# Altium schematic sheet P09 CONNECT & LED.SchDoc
size A2
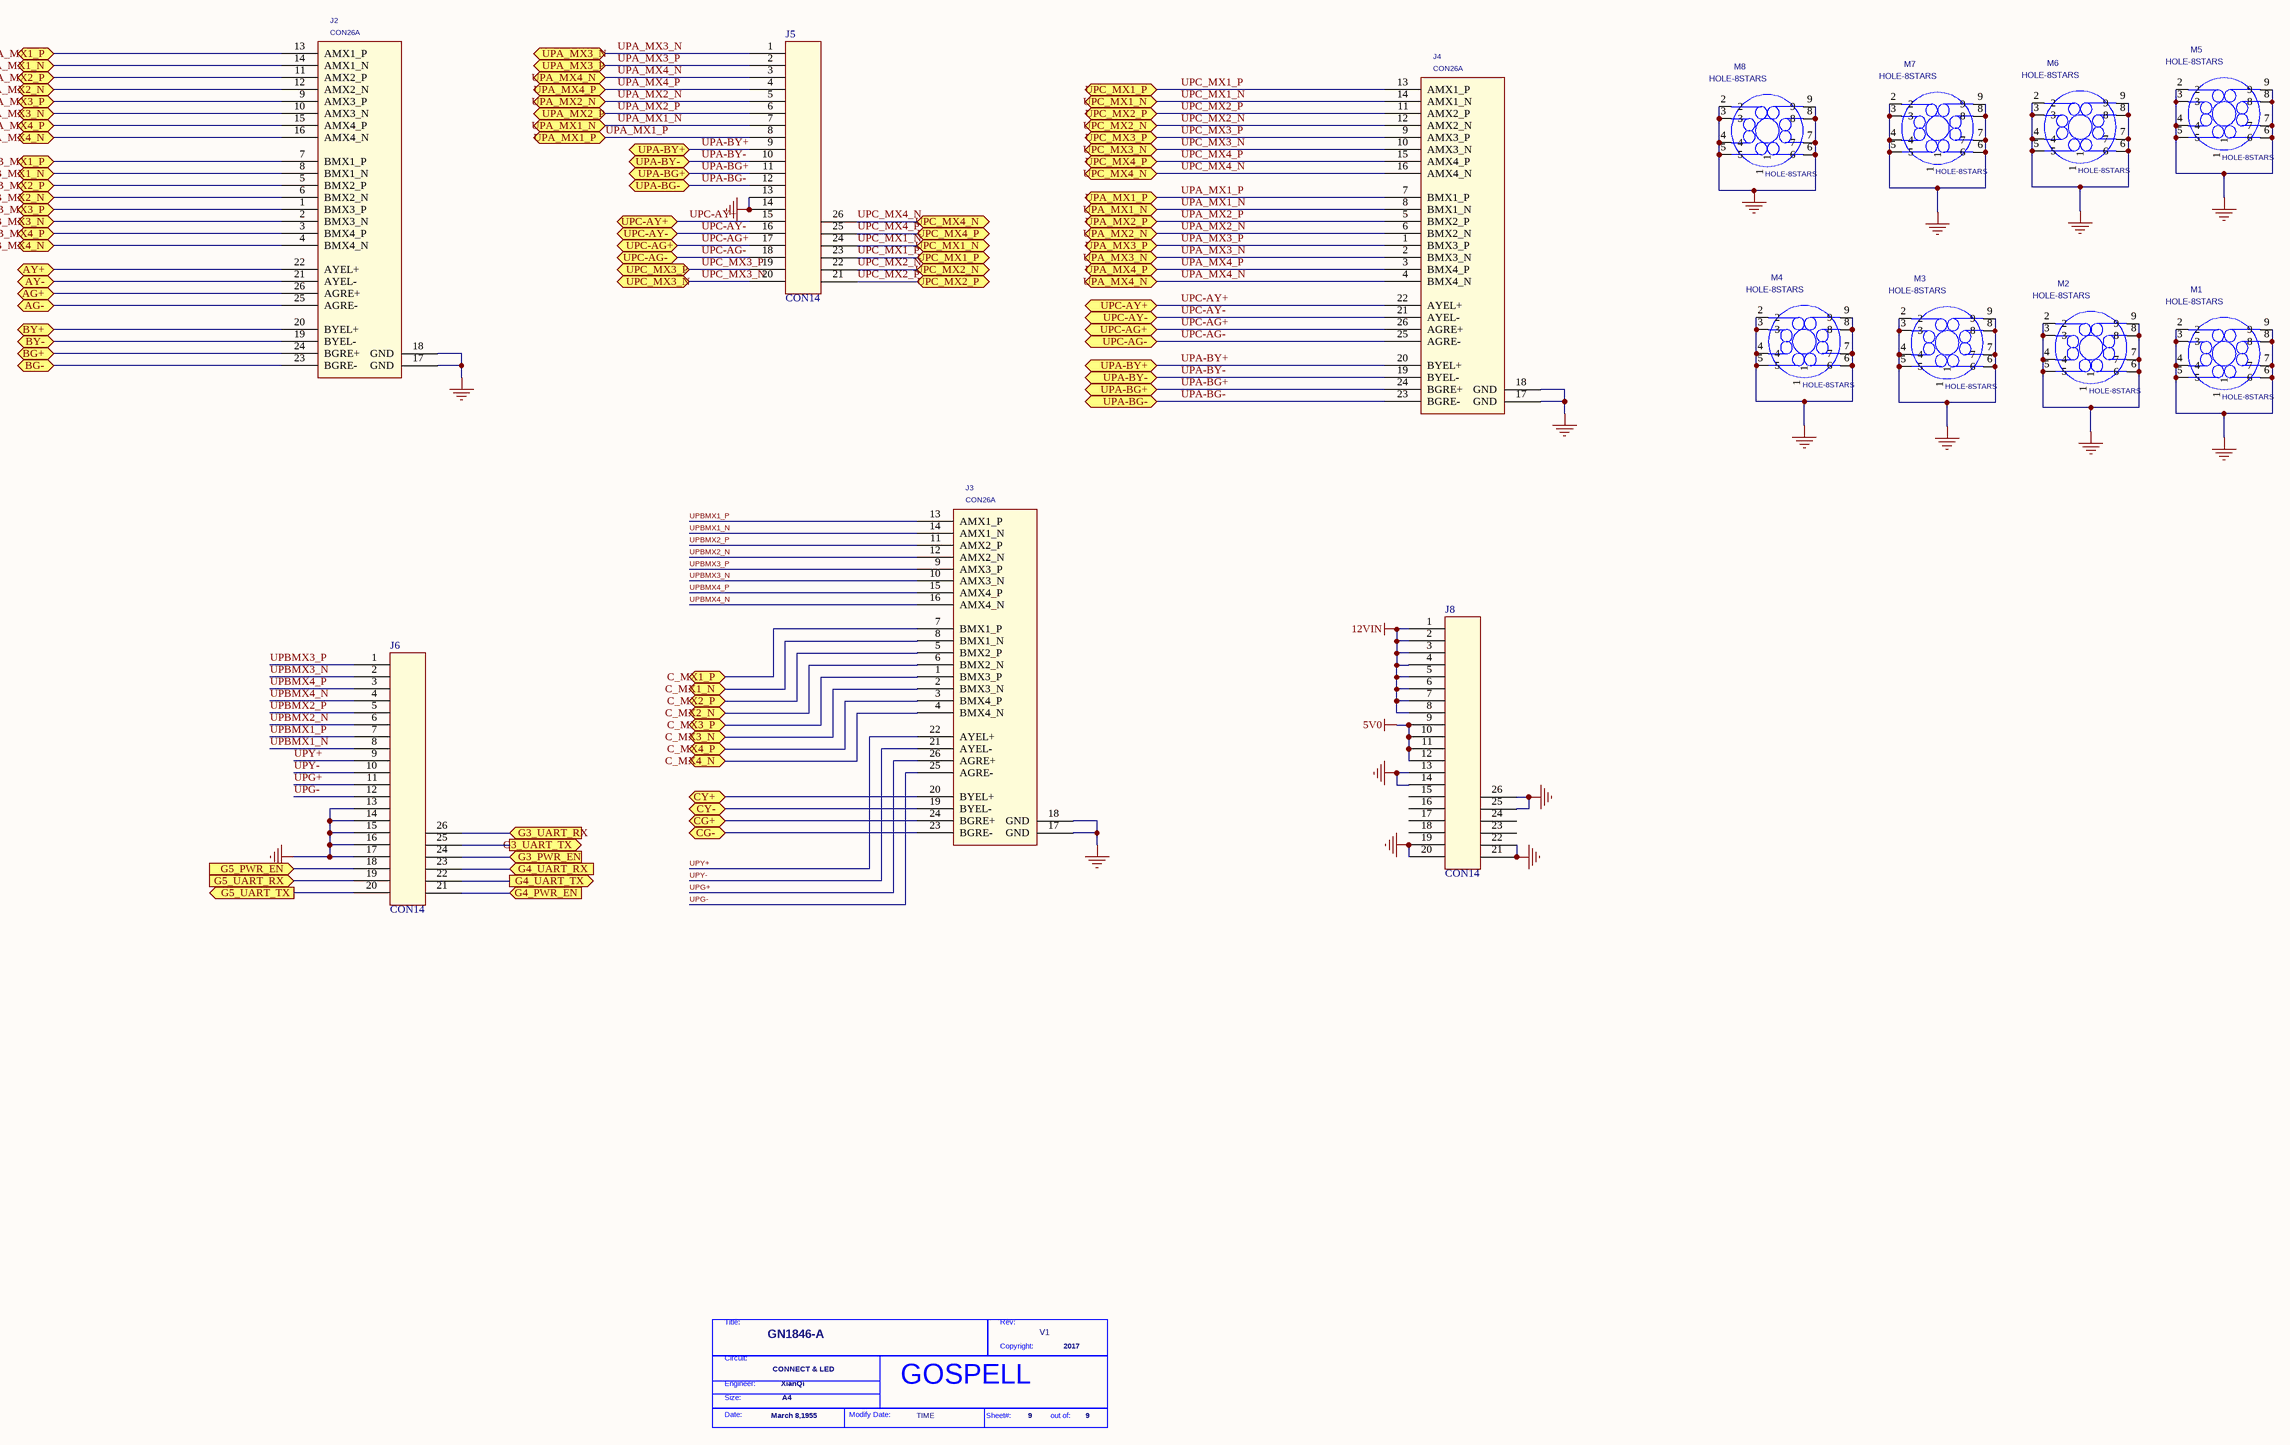
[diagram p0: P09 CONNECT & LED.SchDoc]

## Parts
*  Doc: CONNECT & LED  Page Count: 9  Page Create Date: March 8,1955  Page Size: A4  RevCode: V1  Title: GN1846-A  Copyright: 2017  Engineer: XianQi  Page Modify Date: TIME  (hidden comment: GOSPELL)  (graphical)
J2  CON26A  [HERDER2X13]
J3  CON26A  [HERDER2X13]
J4  CON26A  [HERDER2X13]
J5  CON14  [HERDER13X2-2.0]
J6  CON14  [HERDER13X2-2.0]
J8  CON14  [HERDER13X2-2.0]
M1  HOLE-8STARS  [HK]
M2  HOLE-8STARS  [HK]
M3  HOLE-8STARS  [HK]
M4  HOLE-8STARS  [HK]
M5  HOLE-8STARS  [HK]
M6  HOLE-8STARS  [HK]
M7  HOLE-8STARS  [HK]
M8  HOLE-8STARS  [HK]

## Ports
A_MX1_N (bidir), A_MX1_P (bidir), A_MX2_N (bidir), A_MX2_P (bidir), A_MX3_N (bidir), A_MX3_P (bidir), A_MX4_N (bidir), A_MX4_P (bidir), AG+ (bidir), AG- (bidir), AY+ (bidir), AY- (bidir), B_MX1_N (bidir), B_MX1_P (bidir), B_MX2_N (bidir), B_MX2_P (bidir), B_MX3_N (bidir), B_MX3_P (bidir), B_MX4_N (bidir), B_MX4_P (bidir), BG+ (bidir), BG- (bidir), BY+ (bidir), BY- (bidir), C_MX1_N (bidir), C_MX1_P (bidir), C_MX2_N (bidir), C_MX2_P (bidir), C_MX3_N (bidir), C_MX3_P (bidir), C_MX4_N (bidir), C_MX4_P (bidir), CG+ (bidir), CG- (bidir), CY+ (bidir), CY- (bidir), G3_PWR_EN (in), G3_UART_RX (in), G3_UART_TX (out), G4_PWR_EN (in), G4_UART_RX (in), G4_UART_TX (out), G5_PWR_EN (in), G5_UART_RX (in), G5_UART_TX (out), UPA-BG+ (bidir), UPA-BG- (bidir), UPA-BY+ (bidir), UPA-BY- (bidir), UPA_MX1_N (bidir), UPA_MX1_P (bidir), UPA_MX2_N (bidir), UPA_MX2_P (bidir), UPA_MX3_N (bidir), UPA_MX3_P (bidir), UPA_MX4_N (bidir), UPA_MX4_P (bidir), UPC-AG+ (bidir), UPC-AG- (bidir), UPC-AY+ (bidir), UPC-AY- (bidir), UPC_MX1_N (bidir), UPC_MX1_P (bidir), UPC_MX2_N (bidir), UPC_MX2_P (bidir), UPC_MX3_N (bidir), UPC_MX3_P (bidir), UPC_MX4_N (bidir), UPC_MX4_P (bidir)

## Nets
5V0: J8.9 J8.10 J8.11 J8.12
12VIN: J8.1 J8.2 J8.3 J8.4 J8.5 J8.6 J8.7 J8.8
GND: J2.17(GND) J2.18(GND) J3.17(GND) J3.18(GND) J4.17(GND) J4.18(GND) J5.13 J5.14 J6.13 J6.14 J6.15 J6.16 J6.17 J8.13 J8.14 J8.19 J8.20 J8.21 J8.22 J8.25 J8.26 M1.2 M1.3 M1.4 M1.5 M1.6 M1.7 M1.8 M1.9 M2.2 M2.3 M2.4 M2.5 M2.6 M2.7 M2.8 M2.9 M3.2 M3.3 M3.4 M3.5 M3.6 M3.7 M3.8 M3.9 M4.2 M4.3 M4.4 M4.5 M4.6 M4.7 M4.8 M4.9 M5.2 M5.3 M5.4 M5.5 M5.6 M5.7 M5.8 M5.9 M6.2 M6.3 M6.4 M6.5 M6.6 M6.7 M6.8 M6.9 M7.2 M7.3 M7.4 M7.5 M7.6 M7.7 M7.8 M7.9 M8.2 M8.3 M8.4 M8.5 M8.6 M8.7 M8.8 M8.9
A_MX1_N: J2.14(AMX1_N) ; port A_MX1_N
A_MX1_P: J2.13(AMX1_P) ; port A_MX1_P
A_MX2_N: J2.12(AMX2_N) ; port A_MX2_N
A_MX2_P: J2.11(AMX2_P) ; port A_MX2_P
A_MX3_N: J2.10(AMX3_N) ; port A_MX3_N
A_MX3_P: J2.9(AMX3_P) ; port A_MX3_P
A_MX4_N: J2.16(AMX4_N) ; port A_MX4_N
A_MX4_P: J2.15(AMX4_P) ; port A_MX4_P
AG+: J2.26(AGRE+) ; port AG+
AG-: J2.25(AGRE-) ; port AG-
AY+: J2.22(AYEL+) ; port AY+
AY-: J2.21(AYEL-) ; port AY-
B_MX1_N: J2.8(BMX1_N) ; port B_MX1_N
B_MX1_P: J2.7(BMX1_P) ; port B_MX1_P
B_MX2_N: J2.6(BMX2_N) ; port B_MX2_N
B_MX2_P: J2.5(BMX2_P) ; port B_MX2_P
B_MX3_N: J2.2(BMX3_N) ; port B_MX3_N
B_MX3_P: J2.1(BMX3_P) ; port B_MX3_P
B_MX4_N: J2.4(BMX4_N) ; port B_MX4_N
B_MX4_P: J2.3(BMX4_P) ; port B_MX4_P
BG+: J2.24(BGRE+) ; port BG+
BG-: J2.23(BGRE-) ; port BG-
BY+: J2.20(BYEL+) ; port BY+
BY-: J2.19(BYEL-) ; port BY-
C_MX1_N: J3.8(BMX1_N) ; port C_MX1_N
C_MX1_P: J3.7(BMX1_P) ; port C_MX1_P
C_MX2_N: J3.6(BMX2_N) ; port C_MX2_N
C_MX2_P: J3.5(BMX2_P) ; port C_MX2_P
C_MX3_N: J3.2(BMX3_N) ; port C_MX3_N
C_MX3_P: J3.1(BMX3_P) ; port C_MX3_P
C_MX4_N: J3.4(BMX4_N) ; port C_MX4_N
C_MX4_P: J3.3(BMX4_P) ; port C_MX4_P
CG+: J3.24(BGRE+) ; port CG+
CG-: J3.23(BGRE-) ; port CG-
CY+: J3.20(BYEL+) ; port CY+
CY-: J3.19(BYEL-) ; port CY-
G3_PWR_EN: J6.24 ; port G3_PWR_EN
G3_UART_RX: J6.26 ; port G3_UART_RX
G3_UART_TX: J6.25 ; port G3_UART_TX
G4_PWR_EN: J6.21 ; port G4_PWR_EN
G4_UART_RX: J6.23 ; port G4_UART_RX
G4_UART_TX: J6.22 ; port G4_UART_TX
G5_PWR_EN: J6.18 ; port G5_PWR_EN
G5_UART_RX: J6.19 ; port G5_UART_RX
G5_UART_TX: J6.20 ; port G5_UART_TX
UPA-BG+: J4.24(BGRE+) J5.11 ; port UPA-BG+
UPA-BG-: J4.23(BGRE-) J5.12 ; port UPA-BG-
UPA-BY+: J4.20(BYEL+) J5.9 ; port UPA-BY+
UPA-BY-: J4.19(BYEL-) J5.10 ; port UPA-BY-
UPA_MX1_N: J4.8(BMX1_N) J5.7 ; port UPA_MX1_N
UPA_MX1_P: J4.7(BMX1_P) J5.8 ; port UPA_MX1_P
UPA_MX2_N: J4.6(BMX2_N) J5.5 ; port UPA_MX2_N
UPA_MX2_P: J4.5(BMX2_P) J5.6 ; port UPA_MX2_P
UPA_MX3_N: J4.2(BMX3_N) J5.1 ; port UPA_MX3_N
UPA_MX3_P: J4.1(BMX3_P) J5.2 ; port UPA_MX3_P
UPA_MX4_N: J4.4(BMX4_N) J5.3 ; port UPA_MX4_N
UPA_MX4_P: J4.3(BMX4_P) J5.4 ; port UPA_MX4_P
UPBMX1_N: J3.14(AMX1_N) J6.8
UPBMX1_P: J3.13(AMX1_P) J6.7
UPBMX2_N: J3.12(AMX2_N) J6.6
UPBMX2_P: J3.11(AMX2_P) J6.5
UPBMX3_N: J3.10(AMX3_N) J6.2
UPBMX3_P: J3.9(AMX3_P) J6.1
UPBMX4_N: J3.16(AMX4_N) J6.4
UPBMX4_P: J3.15(AMX4_P) J6.3
UPC-AG+: J4.26(AGRE+) J5.17 ; port UPC-AG+
UPC-AG-: J4.25(AGRE-) J5.18 ; port UPC-AG-
UPC-AY+: J4.22(AYEL+) J5.15 ; port UPC-AY+
UPC-AY-: J4.21(AYEL-) J5.16 ; port UPC-AY-
UPC_MX1_N: J4.14(AMX1_N) J5.24 ; port UPC_MX1_N
UPC_MX1_P: J4.13(AMX1_P) J5.23 ; port UPC_MX1_P
UPC_MX2_N: J4.12(AMX2_N) J5.22 ; port UPC_MX2_N
UPC_MX2_P: J4.11(AMX2_P) J5.21 ; port UPC_MX2_P
UPC_MX3_N: J4.10(AMX3_N) J5.20 ; port UPC_MX3_N
UPC_MX3_P: J4.9(AMX3_P) J5.19 ; port UPC_MX3_P
UPC_MX4_N: J4.16(AMX4_N) J5.26 ; port UPC_MX4_N
UPC_MX4_P: J4.15(AMX4_P) J5.25 ; port UPC_MX4_P
UPG+: J3.26(AGRE+) J6.11
UPG-: J3.25(AGRE-) J6.12
UPY+: J3.22(AYEL+) J6.9
UPY-: J3.21(AYEL-) J6.10

Not connected (* = marked no-connect by the designer): J8 15(14) 16(14) 17(14) 18(14) 23(14) 24(14); M1 1; M2 1; M3 1; M4 1; M5 1; M6 1; M7 1; M8 1

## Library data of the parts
J2-J4 = CON26A_0
M1-M8 = GEN35: Layer: Top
